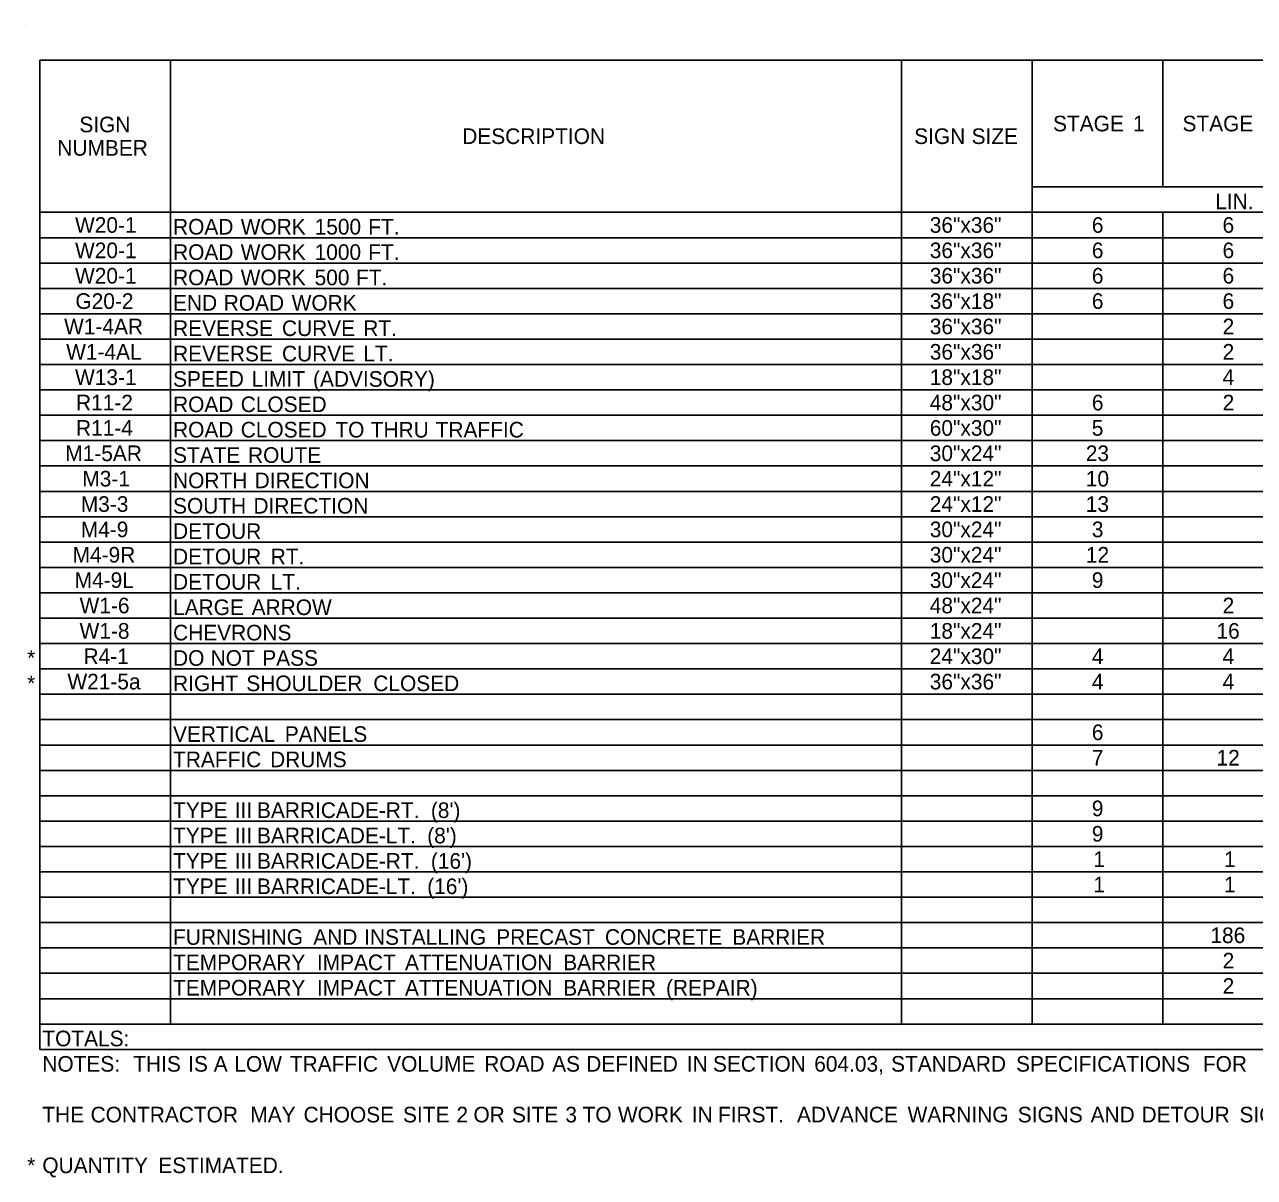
# Model space of a CAD drawing. Extents: x 1955554 to 1962042, y 565952 to 568347.
# Drawn here: x 1956894.1 to 1957366.6, y 566535.5 to 566978.6 of the extents above; entities that cross this region are included whole.
import ezdxf

# ---------------------------------------------------------------- set-up
doc = ezdxf.new("R2010")
doc.units = 0
doc.layers.add('Default', color=7, linetype='Continuous')

msp = doc.modelspace()

# ---------------------------------------------------------------- linework, layer by layer
at = {"layer": 'Default'}
for p, q in [((1956894.11, 566978.56), (1956894.11, 566978.56)), ((1956899.96, 566964.91), (1958067.03, 566964.91)), ((1956899.96, 566584.66), (1956899.96, 566964.91)), ((1956899.96, 566584.66), (1956899.96, 566964.91)), ((1956950.17, 566594.41), (1956950.17, 566964.91)), ((1957230.97, 566594.41), (1957230.97, 566964.91)), ((1957281.18, 566594.41), (1957281.18, 566964.91)), ((1957331.4, 566916.16), (1957331.4, 566964.91)), ((1957281.18, 566916.16), (1957482.03, 566916.16)), ((1956899.96, 566906.41), (1958067.03, 566906.41)), ((1956950.17, 566594.41), (1956950.17, 566906.41)), ((1957230.97, 566594.41), (1957230.97, 566906.41)), ((1957281.18, 566594.41), (1957281.18, 566906.41)), ((1957331.4, 566594.41), (1957331.4, 566906.41)), ((1957331.4, 566594.41), (1957331.4, 566906.41)), ((1956899.96, 566896.66), (1958067.03, 566896.66)), ((1956899.96, 566886.91), (1958067.03, 566886.91)), ((1956899.96, 566877.16), (1958067.03, 566877.16)), ((1956899.96, 566867.41), (1958067.03, 566867.41)), ((1956899.96, 566857.66), (1958067.03, 566857.66)), ((1956899.96, 566847.91), (1958067.03, 566847.91)), ((1956899.96, 566838.16), (1958067.03, 566838.16)), ((1956899.96, 566828.41), (1958067.03, 566828.41)), ((1956899.96, 566818.66), (1958067.03, 566818.66)), ((1956899.96, 566808.91), (1958067.03, 566808.91)), ((1956899.96, 566799.16), (1958067.03, 566799.16)), ((1956899.96, 566789.41), (1958067.03, 566789.41)), ((1956899.96, 566779.66), (1958067.03, 566779.66)), ((1956899.96, 566769.91), (1958067.03, 566769.91)), ((1956899.96, 566760.16), (1958067.03, 566760.16)), ((1956899.96, 566750.41), (1958067.03, 566750.41)), ((1956899.96, 566740.66), (1958067.03, 566740.66)), ((1956899.96, 566730.91), (1958067.03, 566730.91)), ((1956899.96, 566721.16), (1958067.03, 566721.16)), ((1956899.96, 566711.41), (1958067.03, 566711.41)), ((1956899.96, 566701.66), (1958067.03, 566701.66)), ((1956899.96, 566691.91), (1958067.03, 566691.91)), ((1956899.96, 566682.16), (1958067.03, 566682.16)), ((1956899.96, 566672.41), (1958067.03, 566672.41)), ((1956899.96, 566662.66), (1958067.03, 566662.66)), ((1956899.96, 566652.91), (1958067.03, 566652.91)), ((1956899.96, 566643.16), (1958067.03, 566643.16)), ((1956899.96, 566633.41), (1958067.03, 566633.41)), ((1956899.96, 566623.66), (1958067.03, 566623.66)), ((1956899.96, 566613.91), (1958067.03, 566613.91)), ((1956899.96, 566604.16), (1958067.03, 566604.16)), ((1956899.96, 566594.41), (1958067.03, 566594.41)), ((1956899.96, 566584.66), (1958067.03, 566584.66))]:
    msp.add_line(p, q, dxfattribs=at)

# ---------------------------------------------------------------- texts
for s, p in [('SIGN', (1956915.15, 566937.16)), ('STAGE', (1957289.24, 566937.53)), (' 1', (1957317.71, 566937.53)), ('STAGE', (1957338.98, 566937.53)), ('DESCRIPTION', (1957062.26, 566932.66)), ('SIGN', (1957235.89, 566932.66)), (' SIZE', (1957255.72, 566932.66)), ('NUMBER', (1956906.69, 566928.16)), ('LIN.', (1957351.57, 566907.61)), ('W20-1', (1956913.49, 566898.53)), ('ROAD', (1956951.15, 566897.86)), (' WORK', (1956974.92, 566897.86)), (' 1500', (1957003.31, 566897.86)), (' FT.', (1957023.88, 566897.86)), ('36"x36"', (1957241.88, 566898.53)), ('6', (1957304.15, 566898.53)), ('6', (1957354.36, 566898.53)), ('W20-1', (1956913.49, 566888.78)), ('ROAD', (1956951.15, 566888.11)), (' WORK', (1956974.92, 566888.11)), (' 1000', (1957003.31, 566888.11)), (' FT.', (1957023.88, 566888.11)), ('36"x36"', (1957241.88, 566888.78)), ('6', (1957304.15, 566888.78)), ('6', (1957354.36, 566888.78)), ('W20-1', (1956913.49, 566879.03)), ('ROAD', (1956951.15, 566878.36)), (' WORK', (1956974.92, 566878.36)), (' 500', (1957003.31, 566878.36)), (' FT.', (1957019.22, 566878.36)), ('36"x36"', (1957241.88, 566879.03)), ('6', (1957304.15, 566879.03)), ('6', (1957354.36, 566879.03)), ('G20-2', (1956913.64, 566869.28)), ('END', (1956951.15, 566868.61)), (' ROAD', (1956968.4, 566868.61)), (' WORK', (1956994.5, 566868.61)), ('36"x18"', (1957241.88, 566869.28)), ('6', (1957304.15, 566869.28)), ('6', (1957354.36, 566869.28)), ('W1-4AR', (1956909.29, 566859.53)), ('REVERSE', (1956951.15, 566858.86)), (' CURVE', (1956990.77, 566858.86)), (' RT.', (1957022, 566858.86)), ('36"x36"', (1957241.88, 566859.53)), ('2', (1957354.39, 566859.53)), ('W1-4AL', (1956910.08, 566849.78)), ('REVERSE', (1956951.15, 566849.11)), (' CURVE', (1956990.77, 566849.11)), (' LT.', (1957022, 566849.11)), ('36"x36"', (1957241.88, 566849.78)), ('2', (1957354.39, 566849.78)), ('W13-1', (1956913.49, 566840.03)), ('SPEED', (1956951.15, 566839.36)), (' LIMIT', (1956979.12, 566839.36)), (' (ADVISORY)', (1957002.7, 566839.36)), ('18"x18"', (1957241.88, 566840.03)), ('4', (1957354.38, 566840.03)), ('R11-2', (1956913.87, 566830.28)), ('ROAD', (1956951.15, 566829.61)), (' CLOSED', (1956974.92, 566829.61)), ('48"x30"', (1957241.88, 566830.28)), ('6', (1957304.15, 566830.28)), ('2', (1957354.39, 566830.28)), ('R11-4', (1956913.86, 566820.53)), ('60"x30"', (1957241.88, 566820.53)), ('5', (1957304.13, 566820.53)), ('ROAD', (1956951.15, 566819.86)), (' CLOSED', (1956974.92, 566819.86)), (' TO', (1957011.28, 566819.86)), (' THRU', (1957024.87, 566819.86)), (' TRAFFIC', (1957049.81, 566819.86)), ('M1-5AR', (1956909.75, 566810.78)), ('30"x24"', (1957241.88, 566810.78)), ('23', (1957301.82, 566810.78)), ('STATE', (1956951.15, 566810.11)), (' ROUTE', (1956977.72, 566810.11)), ('M3-1', (1956916.29, 566801.03)), ('NORTH', (1956951.15, 566800.36)), (' DIRECTION', (1956980.28, 566800.36)), ('24"x12"', (1957241.88, 566801.03)), ('10', (1957301.83, 566801.03)), ('M3-3', (1956915.71, 566791.28)), ('SOUTH', (1956951.15, 566790.61)), (' DIRECTION', (1956979.81, 566790.61)), ('24"x12"', (1957241.88, 566791.28)), ('13', (1957301.82, 566791.28)), ('M4-9', (1956915.7, 566781.53)), ('DETOUR', (1956951.15, 566780.86)), ('30"x24"', (1957241.88, 566781.53)), ('3', (1957304.15, 566781.53)), ('M4-9R', (1956912.55, 566771.78)), ('DETOUR', (1956951.15, 566771.11)), (' RT.', (1956986.43, 566771.11)), ('30"x24"', (1957241.88, 566771.78)), ('12', (1957301.85, 566771.78)), ('M4-9L', (1956913.34, 566762.03)), ('DETOUR', (1956951.15, 566761.36)), (' LT.', (1956986.43, 566761.36)), ('30"x24"', (1957241.88, 566762.03)), ('9', (1957304.14, 566762.03)), ('W1-6', (1956915.24, 566752.28)), ('LARGE', (1956951.15, 566751.61)), (' ARROW', (1956979.12, 566751.61)), ('48"x24"', (1957241.88, 566752.28)), ('2', (1957354.39, 566752.28)), ('W1-8', (1956915.24, 566742.53)), ('CHEVRONS', (1956951.15, 566741.86)), ('18"x24"', (1957241.88, 566742.53)), ('16', (1957352.03, 566742.53)), ('*', (1956895.08, 566732.11)), ('R4-1', (1956916.75, 566732.78)), ('DO', (1956951.15, 566732.11)), (' NOT', (1956963.35, 566732.11)), (' PASS', (1956983.2, 566732.11)), ('24"x30"', (1957241.88, 566732.78)), ('4', (1957304.16, 566732.78)), ('4', (1957354.38, 566732.78)), ('*', (1956895.08, 566722.36)), ('W21-5a', (1956910.57, 566723.03)), ('RIGHT', (1956951.15, 566722.36)), (' SHOULDER', (1956977.06, 566722.36)), (' CLOSED', (1957025.86, 566722.36)), ('36"x36"', (1957241.88, 566723.03)), ('4', (1957304.16, 566723.03)), ('4', (1957354.38, 566723.03)), ('VERTICAL', (1956951.15, 566702.86)), (' PANELS', (1956991.85, 566702.86)), ('6', (1957304.15, 566703.53)), ('TRAFFIC', (1956951.15, 566693.11)), (' DRUMS', (1956986.21, 566693.11)), ('7', (1957304.15, 566693.78)), ('12', (1957352.06, 566693.78)), (" (8')", (1957047.97, 566673.61)), ('9', (1957304.14, 566674.28)), ('TYPE', (1956951.15, 566673.61)), (' III', (1956972.6, 566673.61)), (' BARRICADE-RT.', (1956981.16, 566673.61)), ('9', (1957304.14, 566664.53)), ('TYPE', (1956951.15, 566663.86)), (' III', (1956972.6, 566663.86)), (' BARRICADE-LT.', (1956981.16, 566663.86)), (" (8')", (1957046.57, 566663.86)), ('TYPE', (1956951.15, 566654.11)), (' III', (1956972.6, 566654.11)), (' BARRICADE-RT.', (1956981.16, 566654.11)), (" (16')", (1957047.97, 566654.11)), ('1', (1957304.73, 566654.78)), ('1', (1957354.94, 566654.78)), ('TYPE', (1956951.15, 566644.36)), (' III', (1956972.6, 566644.36)), (' BARRICADE-LT.', (1956981.16, 566644.36)), (" (16')", (1957046.57, 566644.36)), ('1', (1957304.73, 566645.03)), ('1', (1957354.94, 566645.03)), ('FURNISHING', (1956951.15, 566624.86)), (' AND', (1957002.79, 566624.86)), (' INSTALLING', (1957022.37, 566624.86)), (' PRECAST', (1957073.08, 566624.86)), (' CONCRETE', (1957114.85, 566624.86)), (' BARRIER', (1957163.78, 566624.86)), ('186', (1957349.7, 566625.53)), ('TEMPORARY', (1956951.15, 566615.11)), (' IMPACT', (1957004.19, 566615.11)), (' ATTENUATION', (1957038.02, 566615.11)), (' BARRIER', (1957098.82, 566615.11)), ('2', (1957354.39, 566615.78)), ('TEMPORARY', (1956951.15, 566605.36)), (' IMPACT', (1957004.19, 566605.36)), (' ATTENUATION', (1957038.02, 566605.36)), (' BARRIER', (1957098.82, 566605.36)), (' (REPAIR)', (1957138.31, 566605.36)), ('2', (1957354.39, 566606.03)), ('TOTALS:', (1956900.93, 566585.86)), ('NOTES:', (1956900.93, 566576.11)), ('  THIS', (1956931.41, 566576.11)), (' IS', (1956954.73, 566576.11)), (' A', (1956964.54, 566576.11)), (' LOW', (1956972.47, 566576.11)), (' TRAFFIC', (1956993.8, 566576.11)), (' VOLUME', (1957031.19, 566576.11)), (' ROAD', (1957068.47, 566576.11)), (' AS', (1957094.57, 566576.11)), (' DEFINED', (1957107.65, 566576.11)), (' IN', (1957146.33, 566576.11)), (' SECTION', (1957156.35, 566576.11)), (' 604.03,', (1957195.26, 566576.11)), (' STANDARD', (1957224.8, 566576.11)), (' SPECIFICATIONS', (1957272.8, 566576.11)), (' FOR', (1957344.57, 566576.11)), ('THE', (1956900.93, 566556.61)), (' CONTRACTOR', (1956917.25, 566556.61)), (' MAY', (1956978.62, 566556.61)), (' CHOOSE', (1956999.06, 566556.61)), (' SITE', (1957037.27, 566556.61)), (' 2', (1957057.79, 566556.61)), (' OR', (1957064.33, 566556.61)), (' SITE', (1957079.12, 566556.61)), (' 3', (1957099.64, 566556.61)), (' TO', (1957106.25, 566556.61)), (' WORK', (1957119.84, 566556.61)), (' IN', (1957148.23, 566556.61)), (' FIRST.', (1957158.26, 566556.61)), ('  ADVANCE', (1957186.4, 566556.61)), (' WARNING', (1957231.14, 566556.61)), (' SIGNS', (1957273.46, 566556.61)), (' AND', (1957301.44, 566556.61)), (' DETOUR', (1957321.02, 566556.61)), (' SIGNS', (1957358.64, 566556.61)), ('*', (1956895.08, 566537.11)), ('QUANTITY', (1956900.93, 566537.11)), (' ESTIMATED.', (1956943.26, 566537.11))]:
    msp.add_text(s, height=6, dxfattribs=at).set_placement(p)

doc.saveas('drawing.dxf')
